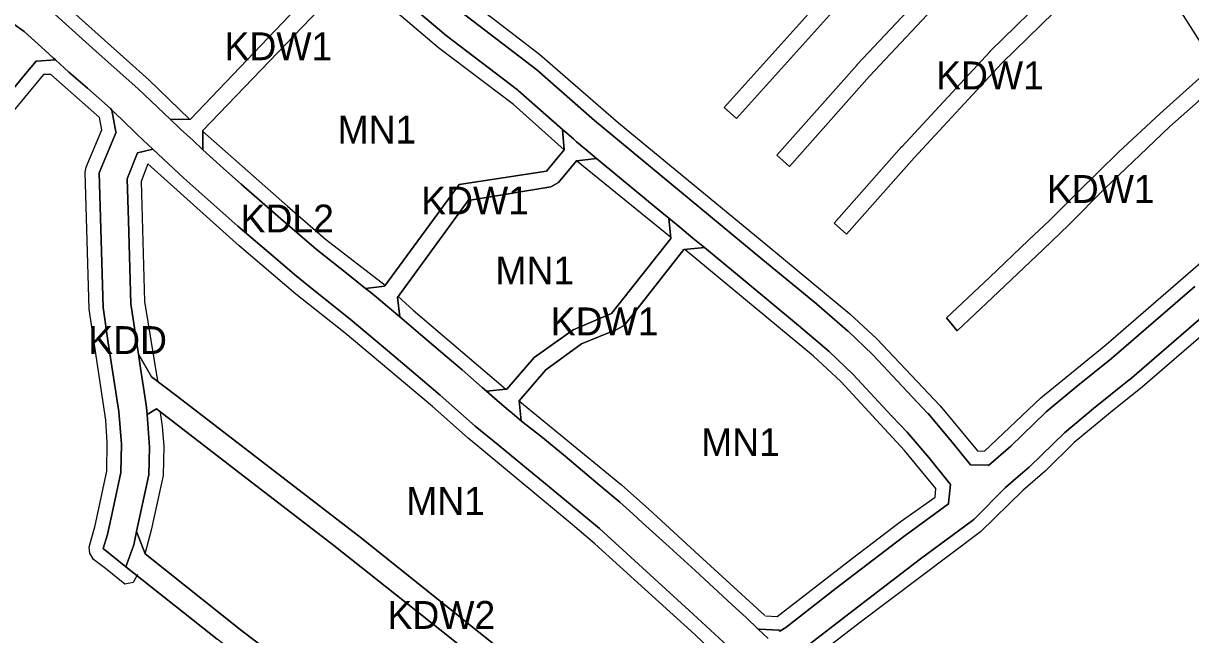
# Model space of a CAD drawing. Extents: x -284239 to -281592, y 34477 to 37267.
# Drawn here: x -283512.6 to -283094, y 35270.9 to 35490.3 of the extents above; entities that cross this region are included whole.
import ezdxf

# ---------------------------------------------------------------- set-up
doc = ezdxf.new("R2010")
doc.units = 0
for name, color, linetype in [('linie_rozgraniczajace', 7, 'Continuous'), ('linie_zabudowy_nieprzekraczalne', 7, 'Continuous'), ('oznaczenia_przeznaczen', 7, 'Continuous')]:
    doc.layers.add(name, color=color, linetype=linetype)

msp = doc.modelspace()

# ---------------------------------------------------------------- linework, layer by layer
at = {"layer": 'linie_rozgraniczajace'}
for points in [[(-283261.298, 35460.15), (-283210.762, 35516.507), (-283206.679, 35521.057), (-283202.803, 35525.377), (-283198.107, 35530.61), (-283194.076, 35535.102), (-283181.848, 35548.728), (-283169.95, 35561.785), (-283171.609, 35566.589), (-283170.52, 35566.632), (-283166.417, 35565.662), (-283164.569, 35565.225), (-283162.307, 35563.981), (-283160.442, 35562.955), (-283156.878, 35559.563), (-283164.204, 35558.906), (-283177.398, 35544.705), (-283190.045, 35530.61), (-283194.076, 35526.119), (-283198.618, 35521.057), (-283202.803, 35516.393), (-283206.296, 35512.5), (-283256.831, 35456.145)], [(-283242.392, 35442.939), (-283213.619, 35475.417), (-283213.588, 35475.438), (-283213.562, 35475.479), (-283179.793, 35511.495), (-283161.166, 35532.63), (-283149.95, 35545.248), (-283149.998, 35545.727), (-283149.736, 35552.671), (-283149.639, 35552.65), (-283146.347, 35549.301), (-283144.476, 35547.397), (-283142.132, 35545.012), (-283138.586, 35541.406), (-283145.528, 35541.192), (-283156.673, 35528.655), (-283175.322, 35507.493), (-283175.356, 35507.469), (-283175.384, 35507.425), (-283209.156, 35471.406), (-283237.901, 35438.96)], [(-283221.889, 35418.595), (-283197.68, 35445.979), (-283197.655, 35445.997), (-283197.633, 35446.031), (-283166.082, 35480.096), (-283166.025, 35480.135), (-283165.984, 35480.197), (-283142.436, 35503.348), (-283142.351, 35503.404), (-283142.303, 35503.471), (-283123.015, 35520.27), (-283123.015, 35526.596), (-283119.508, 35523.325), (-283118.003, 35521.92), (-283115.117, 35519.192), (-283111.325, 35515.608), (-283118.634, 35515.726), (-283119.023, 35515.79), (-283138.294, 35499.006), (-283161.727, 35475.967), (-283193.208, 35441.979), (-283217.394, 35414.621)], [(-283459.881, 35455.783), (-283452.711, 35455.963), (-283399.464, 35511.822), (-283399.464, 35511.924), (-283399.734, 35518.856), (-283397.587, 35516.882), (-283397.44, 35516.75), (-283395.961, 35515.497), (-283391.099, 35511.382), (-283387.556, 35508.383), (-283394.625, 35507.71), (-283448.28, 35451.829), (-283448.198, 35444.961), (-283451.752, 35448.213), (-283456.211, 35452.291), (-283456.735, 35452.771)], [(-283448.28, 35451.829), (-283394.625, 35507.71), (-283387.556, 35508.383), (-283361.724, 35486.517), (-283361.651, 35486.472), (-283361.462, 35486.31), (-283335.431, 35466.436), (-283335.282, 35466.336), (-283335.195, 35466.214), (-283319.25, 35452.214), (-283318.647, 35444.882), (-283324.984, 35437.311), (-283356.337, 35432.416), (-283382.95, 35396.045), (-283383.06, 35396.036), (-283389.857, 35395.197), (-283396.132, 35400.193), (-283407.596, 35409.26), (-283420.363, 35420.255), (-283434.537, 35432.552), (-283440.842, 35438.232), (-283448.198, 35444.961)], [(-283181.627, 35384.658), (-283166.18, 35399.031), (-283152.11, 35412.496), (-283144.622, 35419.515), (-283134.414, 35429.79), (-283119.94, 35444.062), (-283104.997, 35457.997), (-283088.711, 35472.604), (-283084.701, 35475.893), (-283083.567, 35482.594), (-283081.071, 35478.87), (-283077.753, 35473.919), (-283076.594, 35472.189), (-283075.196, 35470.539), (-283081.391, 35470.733), (-283091.364, 35462.228), (-283101.438, 35453.229), (-283112.217, 35442.987), (-283124.675, 35431.133), (-283137.738, 35418.003), (-283146.972, 35409.037), (-283165.072, 35391.878), (-283177.799, 35379.957)], [(-283485.454, 35436.649), (-283479.354, 35451.217), (-283479.369, 35451.4), (-283480.866, 35459.201), (-283477.411, 35455.858), (-283471.742, 35450.373), (-283469.806, 35448.558), (-283466.213, 35445.188), (-283471.669, 35443.866), (-283475.4, 35434.466), (-283474.871, 35419.584), (-283474.077, 35389.686), (-283471.305, 35371.537), (-283470.537, 35366.511), (-283468.764, 35354.903), (-283468.388, 35352.445), (-283468.203, 35349.947), (-283467.33, 35338.158), (-283467.595, 35328.236), (-283471.971, 35307.953), (-283472.999, 35303.193), (-283473.019, 35303.101), (-283475.832, 35295.276), (-283483.999, 35301.778), (-283482.411, 35306.871), (-283480.427, 35316.132), (-283477.649, 35329.096), (-283477.384, 35339.282), (-283478.31, 35350.99), (-283482.147, 35375.597), (-283483.999, 35388.363)], [(-283389.857, 35395.197), (-283383.06, 35396.036), (-283382.95, 35396.045), (-283356.337, 35432.416), (-283324.984, 35437.311), (-283318.647, 35444.882), (-283319.25, 35452.214), (-283315.365, 35448.803), (-283314.313, 35447.882), (-283314.217, 35447.797), (-283310.882, 35445.032), (-283307.027, 35441.835), (-283314.136, 35441.015), (-283314.264, 35440.98), (-283320.751, 35433.21), (-283323.396, 35431.622), (-283353.03, 35426.727), (-283378.418, 35391.967), (-283377.606, 35384.925), (-283381.286, 35388.04), (-283385.932, 35391.97), (-283387.951, 35393.679)], [(-283378.418, 35391.967), (-283353.03, 35426.727), (-283323.396, 35431.622), (-283320.751, 35433.21), (-283314.264, 35440.98), (-283314.136, 35441.015), (-283307.027, 35441.835), (-283283.671, 35422.469), (-283281.159, 35420.396), (-283280.401, 35413.102), (-283280.416, 35413.038), (-283301.701, 35386.114), (-283315.459, 35380.293), (-283329.482, 35370.371), (-283339.216, 35359.015), (-283339.404, 35358.994), (-283346.478, 35358.268), (-283348.088, 35359.652), (-283355.279, 35365.905), (-283360.594, 35370.49), (-283370.13, 35378.672), (-283374.403, 35382.215), (-283377.606, 35384.925)], [(-283346.478, 35358.268), (-283339.404, 35358.994), (-283339.216, 35359.015), (-283329.482, 35370.371), (-283315.459, 35380.293), (-283301.701, 35386.114), (-283280.416, 35413.038), (-283280.401, 35413.102), (-283281.159, 35420.396), (-283277.19, 35417.12), (-283272.501, 35413.249), (-283268.403, 35409.865), (-283275.639, 35409.133), (-283275.76, 35409.106), (-283297.07, 35382.013), (-283299.584, 35380.558), (-283312.416, 35375.266), (-283325.248, 35366.005), (-283334.773, 35354.82), (-283334.773, 35354.761), (-283334.033, 35347.672), (-283338.02, 35351.008), (-283338.448, 35351.367), (-283342.665, 35354.991)], [(-283334.773, 35354.761), (-283334.773, 35354.82), (-283325.248, 35366.005), (-283312.416, 35375.266), (-283299.584, 35380.558), (-283297.07, 35382.013), (-283275.76, 35409.106), (-283275.639, 35409.133), (-283268.403, 35409.865), (-283253.762, 35397.779), (-283234.587, 35381.906), (-283223.651, 35372.478), (-283215.068, 35364.268), (-283201.231, 35349.42), (-283201.205, 35349.402), (-283201.186, 35349.372), (-283195.688, 35343.624), (-283187.875, 35334.437), (-283180.189, 35324.849), (-283180.899, 35318.034), (-283180.882, 35317.903), (-283196.847, 35306.128), (-283196.89, 35306.091), (-283196.917, 35306.075), (-283221.137, 35287.546), (-283239.236, 35273.513), (-283241.329, 35272.174), (-283241.537, 35272.46), (-283248.7, 35272.865), (-283249.079, 35272.865), (-283253.458, 35277.007), (-283258.46, 35281.593), (-283271.748, 35293.942), (-283282.17, 35303.53), (-283290.559, 35311.086), (-283293.999, 35314.213), (-283298.688, 35318.486), (-283305.88, 35324.426), (-283318.333, 35334.9), (-283326.984, 35342.091), (-283333.341, 35347.094), (-283334.033, 35347.672)], [(-283471.305, 35371.537), (-283466.598, 35363.492), (-283457.276, 35356.348), (-283391.394, 35305.482), (-283321.809, 35249.721), (-283284.37, 35219.029), (-283262.84, 35199.528), (-283256.137, 35199.876), (-283259.102, 35196.143), (-283264.139, 35189.807), (-283267.065, 35186.125), (-283267.966, 35193.166), (-283267.989, 35193.296), (-283287.545, 35211.026), (-283316.782, 35235.169), (-283359.777, 35270.028), (-283401.316, 35302.902), (-283436.506, 35330.022), (-283464.859, 35351.891), (-283468.203, 35349.947), (-283468.388, 35352.445), (-283468.764, 35354.903), (-283470.537, 35366.511)], [(-283471.971, 35307.953), (-283467.595, 35328.236), (-283467.33, 35338.158), (-283468.203, 35349.947), (-283464.859, 35351.891), (-283436.506, 35330.022), (-283401.316, 35302.902), (-283359.777, 35270.028), (-283316.782, 35235.169), (-283287.545, 35211.026), (-283267.989, 35193.296), (-283267.966, 35193.166), (-283267.065, 35186.125), (-283287.997, 35159.793), (-283294.778, 35159.039), (-283328.82, 35188.404), (-283371.551, 35224.453), (-283413.223, 35256.402), (-283434.257, 35272.277), (-283468.923, 35299.941)], [(-283475.832, 35295.276), (-283473.019, 35303.101), (-283472.999, 35303.193), (-283471.971, 35307.953), (-283468.923, 35299.941), (-283434.257, 35272.277), (-283413.223, 35256.402), (-283371.551, 35224.453), (-283328.82, 35188.404), (-283294.778, 35159.039), (-283287.997, 35159.793), (-283291.111, 35155.876), (-283296.191, 35149.484), (-283296.144, 35149.444), (-283299.168, 35145.536), (-283299.981, 35152.552), (-283300.009, 35152.798), (-283336.758, 35184.7), (-283374.858, 35216.582), (-283390.336, 35228.687), (-283443.121, 35269.234)]]:
    msp.add_lwpolyline(points, close=True, dxfattribs=at)
for points in [[(-283210.762, 35516.507), (-283261.298, 35460.15), (-283256.831, 35456.145), (-283206.296, 35512.5)], [(-283399.464, 35511.822), (-283452.711, 35455.963), (-283459.881, 35455.783), (-283471.482, 35466.892), (-283485.395, 35479.242), (-283497.484, 35490.185), (-283503.633, 35495.708)], [(-283201.186, 35349.372), (-283201.205, 35349.402), (-283201.231, 35349.42), (-283215.068, 35364.268), (-283223.651, 35372.478), (-283234.587, 35381.906), (-283253.762, 35397.779), (-283268.403, 35409.865), (-283272.501, 35413.249), (-283277.19, 35417.12), (-283281.159, 35420.396), (-283283.671, 35422.469), (-283307.027, 35441.835), (-283310.882, 35445.032), (-283314.217, 35447.797), (-283314.313, 35447.882), (-283315.365, 35448.803), (-283319.25, 35452.214), (-283335.195, 35466.214), (-283335.282, 35466.336), (-283335.431, 35466.436), (-283361.462, 35486.31), (-283361.651, 35486.472), (-283361.724, 35486.517), (-283387.556, 35508.383)], [(-283179.793, 35511.495), (-283213.562, 35475.479), (-283213.588, 35475.438), (-283213.619, 35475.417), (-283242.392, 35442.939)], [(-283242.392, 35442.939), (-283237.901, 35438.96), (-283209.156, 35471.406), (-283175.384, 35507.425)], [(-283142.436, 35503.348), (-283165.984, 35480.197), (-283166.025, 35480.135), (-283166.082, 35480.096), (-283197.633, 35446.031), (-283197.655, 35445.997), (-283197.68, 35445.979), (-283221.889, 35418.595), (-283217.394, 35414.621), (-283193.208, 35441.979), (-283161.727, 35475.967), (-283138.294, 35499.006)], [(-283503.633, 35495.708), (-283497.484, 35490.185), (-283485.395, 35479.242), (-283471.482, 35466.892), (-283459.881, 35455.783), (-283456.735, 35452.771), (-283456.211, 35452.291), (-283451.752, 35448.213), (-283448.198, 35444.961), (-283440.842, 35438.232), (-283434.537, 35432.552), (-283420.363, 35420.255), (-283407.596, 35409.26), (-283396.132, 35400.193), (-283389.857, 35395.197), (-283387.951, 35393.679), (-283385.932, 35391.97), (-283381.286, 35388.04), (-283377.606, 35384.925), (-283374.403, 35382.215), (-283370.13, 35378.672), (-283360.594, 35370.49), (-283355.279, 35365.905), (-283348.088, 35359.652), (-283346.478, 35358.268), (-283342.665, 35354.991), (-283338.448, 35351.367), (-283338.02, 35351.008), (-283334.033, 35347.672), (-283333.341, 35347.094), (-283326.984, 35342.091), (-283318.333, 35334.9), (-283305.88, 35324.426), (-283298.688, 35318.486), (-283293.999, 35314.213), (-283290.559, 35311.086), (-283282.17, 35303.53), (-283271.748, 35293.942), (-283258.46, 35281.593), (-283253.458, 35277.007), (-283249.079, 35272.865), (-283245.518, 35269.496)], [(-283355.39, 35494.257), (-283328.475, 35473.622), (-283307.779, 35455.45), (-283277.295, 35430.174), (-283247.391, 35405.487), (-283228.172, 35389.577), (-283228.104, 35389.518), (-283217.024, 35379.968), (-283216.957, 35379.875), (-283216.833, 35379.794), (-283208.052, 35371.395), (-283207.968, 35371.272), (-283207.85, 35371.19), (-283193.937, 35356.261), (-283188.355, 35350.422), (-283188.164, 35350.214), (-283180.211, 35340.86), (-283180.194, 35340.832), (-283180.118, 35340.748), (-283173.013, 35331.885), (-283166.601, 35331.748), (-283166.526, 35331.665), (-283158.558, 35338.538), (-283146.086, 35350.614), (-283145.826, 35350.85), (-283135.232, 35359.72), (-283135.166, 35359.777), (-283122.401, 35370.041), (-283092.511, 35395.841)], [(-283092.511, 35395.841), (-283122.401, 35370.041), (-283135.166, 35359.777), (-283135.232, 35359.72), (-283145.826, 35350.85), (-283146.086, 35350.614), (-283158.558, 35338.538), (-283166.526, 35331.665), (-283166.601, 35331.748), (-283173.013, 35331.885), (-283180.118, 35340.748), (-283180.194, 35340.832), (-283180.211, 35340.86), (-283188.164, 35350.214), (-283188.355, 35350.422), (-283193.937, 35356.261), (-283207.85, 35371.19), (-283207.968, 35371.272), (-283208.052, 35371.395), (-283216.833, 35379.794), (-283216.957, 35379.875), (-283217.024, 35379.968), (-283228.104, 35389.518), (-283228.172, 35389.577), (-283247.391, 35405.487), (-283277.295, 35430.174), (-283307.779, 35455.45), (-283328.475, 35473.622), (-283355.39, 35494.257)], [(-283516.02, 35490.071), (-283512.308, 35487.34), (-283504.735, 35480.519), (-283501.757, 35477.783), (-283501.114, 35477.189), (-283507.923, 35476.675), (-283507.952, 35476.707), (-283511.807, 35472.138), (-283532.826, 35446.614)], [(-283501.114, 35477.189), (-283501.757, 35477.783), (-283504.735, 35480.519), (-283512.308, 35487.34), (-283516.02, 35490.071)], [(-283532.826, 35446.614), (-283511.807, 35472.138), (-283507.952, 35476.707), (-283507.923, 35476.675), (-283501.114, 35477.189), (-283496.338, 35472.781), (-283489.616, 35466.996), (-283481.383, 35459.701), (-283480.866, 35459.201), (-283479.369, 35451.4), (-283479.354, 35451.217), (-283485.454, 35436.649), (-283483.999, 35388.363), (-283482.147, 35375.597), (-283478.31, 35350.99), (-283477.384, 35339.282), (-283477.649, 35329.096), (-283480.427, 35316.132), (-283482.411, 35306.871), (-283483.999, 35301.778), (-283475.832, 35295.276), (-283443.121, 35269.234)], [(-283258.408, 35265.282), (-283272.425, 35278.258), (-283286.443, 35291.024), (-283306.036, 35308.95), (-283323.336, 35323.332), (-283342.356, 35339.017), (-283350.537, 35345.739), (-283363.147, 35356.89), (-283379.77, 35371.011), (-283395.351, 35384.091), (-283409.003, 35395.034), (-283415.36, 35400.141), (-283422.135, 35405.977), (-283435.683, 35417.545), (-283455.015, 35434.689), (-283466.213, 35445.188), (-283469.806, 35448.558), (-283471.742, 35450.373), (-283477.411, 35455.858), (-283480.866, 35459.201), (-283481.383, 35459.701), (-283489.616, 35466.996), (-283496.338, 35472.781), (-283501.114, 35477.189)], [(-283088.711, 35472.604), (-283104.997, 35457.997), (-283119.94, 35444.062), (-283134.414, 35429.79), (-283144.622, 35419.515), (-283152.11, 35412.496), (-283166.18, 35399.031), (-283181.627, 35384.658), (-283177.799, 35379.957), (-283165.072, 35391.878), (-283146.972, 35409.037), (-283137.738, 35418.003), (-283124.675, 35431.133), (-283112.217, 35442.987), (-283101.438, 35453.229), (-283091.364, 35462.228)], [(-283321.809, 35249.721), (-283391.394, 35305.482), (-283457.276, 35356.348), (-283466.598, 35363.492), (-283471.305, 35371.537), (-283474.077, 35389.686), (-283474.871, 35419.584), (-283475.4, 35434.466), (-283471.669, 35443.866), (-283466.213, 35445.188), (-283455.015, 35434.689), (-283435.683, 35417.545), (-283422.135, 35405.977), (-283415.36, 35400.141), (-283409.003, 35395.034), (-283395.351, 35384.091), (-283379.77, 35371.011), (-283363.147, 35356.89), (-283350.537, 35345.739), (-283342.356, 35339.017), (-283323.336, 35323.332), (-283306.036, 35308.95), (-283286.443, 35291.024), (-283272.425, 35278.258), (-283258.408, 35265.282)], [(-283085.962, 35388.284), (-283115.933, 35362.414), (-283115.964, 35362.396), (-283116.067, 35362.303), (-283128.86, 35352.016), (-283139.267, 35343.3), (-283151.705, 35331.255), (-283151.842, 35331.164), (-283151.917, 35331.06), (-283155.82, 35327.693), (-283160.432, 35323.716), (-283171.683, 35312.335), (-283172.258, 35311.839), (-283190.875, 35298.106), (-283215.037, 35279.622), (-283233.281, 35265.477)], [(-283233.281, 35265.477), (-283215.037, 35279.622), (-283190.875, 35298.106), (-283172.258, 35311.839), (-283171.683, 35312.335), (-283160.432, 35323.716), (-283155.82, 35327.693), (-283151.917, 35331.06), (-283151.842, 35331.164), (-283151.705, 35331.255), (-283139.267, 35343.3), (-283128.86, 35352.016), (-283116.067, 35362.303), (-283115.964, 35362.396), (-283115.933, 35362.414), (-283085.962, 35388.284)], [(-283245.518, 35269.496), (-283249.079, 35272.865), (-283248.7, 35272.865), (-283241.537, 35272.46), (-283241.329, 35272.174), (-283239.236, 35273.513), (-283221.137, 35287.546), (-283196.917, 35306.075), (-283196.89, 35306.091), (-283196.847, 35306.128), (-283180.882, 35317.903), (-283180.899, 35318.034), (-283180.189, 35324.849), (-283187.875, 35334.437), (-283195.688, 35343.624), (-283201.186, 35349.372)]]:
    msp.add_lwpolyline(points, dxfattribs=at)
at = {"layer": 'linie_zabudowy_nieprzekraczalne'}
for points in [[(-283355.523, 35636.02), (-283360.937, 35639.423), (-283371.388, 35646.17), (-283379.59, 35645.641), (-283426.951, 35603.109), (-283443.091, 35588.16), (-283443.355, 35585.117), (-283417.823, 35557.336), (-283402.874, 35542.122), (-283392.423, 35532.399), (-283352.735, 35498.4), (-283344.004, 35491.984), (-283327.335, 35479.151), (-283299.157, 35454.611), (-283245.579, 35410.492), (-283216.21, 35386.018), (-283206.553, 35377.022), (-283183.798, 35353.077), (-283170.437, 35336.871), (-283167.923, 35336.739), (-283147.683, 35355.921), (-283124.399, 35374.905), (-283078.759, 35414.527), (-283054.285, 35435.561)], [(-283399.708, 35511.798), (-283404.726, 35516.59), (-283423.379, 35534.317), (-283438.989, 35550.391), (-283457.907, 35571.557), (-283461.876, 35571.822), (-283483.175, 35553.896), (-283504.077, 35537.492), (-283522.201, 35524.528), (-283519.952, 35516.855), (-283501.696, 35500.715), (-283467.565, 35470.023), (-283453.022, 35455.97)], [(-283085.515, 35475.682), (-283096.618, 35493.174), (-283102.306, 35500.054), (-283118.853, 35515.634)], [(-283318.644, 35444.885), (-283336.86, 35461.16), (-283363.715, 35481.533), (-283394.417, 35507.696)], [(-283471.687, 35292.526), (-283473.207, 35289.655), (-283476.212, 35289.055), (-283483.175, 35294.604), (-283487.408, 35297.911), (-283488.731, 35300.16), (-283488.996, 35302.277), (-283486.879, 35310.016), (-283482.646, 35329.595), (-283482.514, 35339.914), (-283483.043, 35347.918), (-283488.996, 35387.672), (-283490.451, 35436.884), (-283490.054, 35438.67), (-283484.498, 35452.032), (-283485.292, 35456.53), (-283502.754, 35472.008), (-283505.4, 35472.008), (-283529.874, 35442.44)], [(-283448.392, 35451.605), (-283417.823, 35424.713), (-283404.197, 35412.807), (-283382.907, 35396.307)], [(-283280.513, 35413.505), (-283314.249, 35440.998)], [(-283262.786, 35199.853), (-283239.361, 35228.789), (-283239.361, 35233.353), (-283255.104, 35254.784), (-283260.66, 35260.341), (-283271.772, 35270.99), (-283307.624, 35303.534), (-283316.487, 35311.008), (-283353.132, 35341.436), (-283365.832, 35352.746), (-283397.185, 35379.073), (-283414.912, 35393.162), (-283435.153, 35410.492), (-283467.961, 35439.861), (-283470.343, 35433.511), (-283469.152, 35390.516), (-283464.531, 35362.043)], [(-283246.505, 35277.605), (-283242.271, 35277.472), (-283215.284, 35298.374), (-283198.218, 35311.405), (-283185.65, 35320.269), (-283185.386, 35323.312), (-283196.631, 35337.004), (-283219.517, 35361.742), (-283229.307, 35370.804), (-283275.222, 35409.007)], [(-283388.431, 35400.589), (-283388.322, 35400.504)], [(-283378.277, 35392.338), (-283372.843, 35387.407), (-283339.648, 35359.133)], [(-283081.14, 35382.909), (-283084.315, 35383.174), (-283111.302, 35359.89), (-283122.812, 35350.63), (-283135.776, 35339.848), (-283146.227, 35329.529), (-283154.165, 35322.65), (-283169.379, 35307.767), (-283212.373, 35275.422), (-283230.233, 35261.663), (-283230.762, 35258.885), (-283213.299, 35235.47), (-283197.028, 35210.202), (-283194.117, 35205.109), (-283190.413, 35193.864), (-283186.841, 35177.724), (-283184.734, 35159.504)], [(-283334.621, 35354.635), (-283298.099, 35324.634), (-283288.309, 35315.903), (-283270.317, 35299.433), (-283246.769, 35277.737)], [(-283463.473, 35350.666), (-283462.812, 35345.639), (-283462.273, 35338.525), (-283462.405, 35328.074), (-283466.771, 35308.429), (-283468.897, 35300.263)]]:
    msp.add_lwpolyline(points, dxfattribs=at)

# ---------------------------------------------------------------- texts
at = {"layer": 'oznaczenia_przeznaczen'}
for s, p in [('KDW1', (-283440.441, 35477.079)), ('KDW1', (-283185.281, 35466.626)), ('MN1', (-283399.918, 35447.175)), ('KDW1', (-283145.568, 35425.863)), ('KDW1', (-283369.915, 35421.727)), ('KDL2', (-283434.682, 35415.255)), ('MN1', (-283343.314, 35396.609)), ('KDW1', (-283323.471, 35378.328)), ('KDD', (-283489.32, 35371.622)), ('MN1', (-283269.558, 35334.977)), ('MN1', (-283375.3, 35313.874)), ('KDW2', (-283382.02, 35272.968))]:
    msp.add_text(s, height=10, dxfattribs=at).set_placement(p)

doc.saveas('drawing.dxf')
